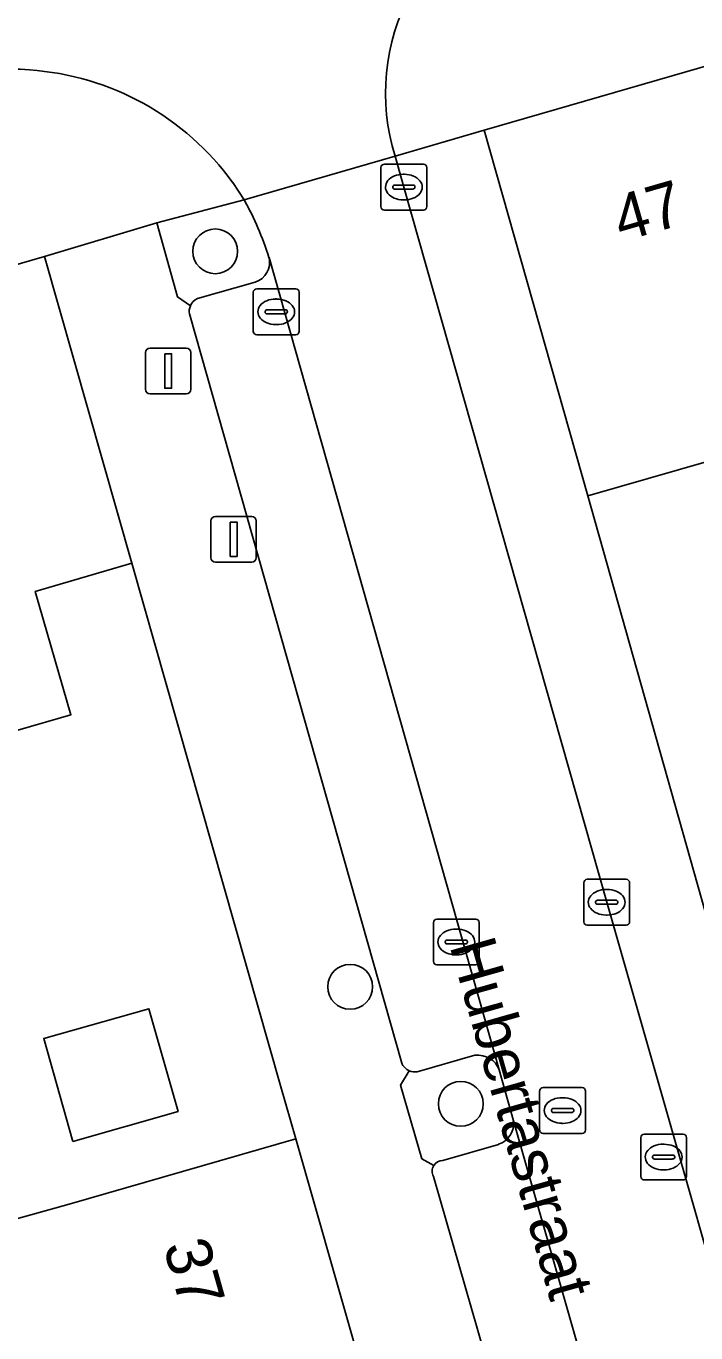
# Model space of a CAD drawing. Extents: x 159716 to 160783, y 383290 to 384031.
# Drawn here: x 160271.18 to 160285.8, y 383552.15 to 383580.67 of the extents above; entities that cross this region are included whole.
import ezdxf

# ---------------------------------------------------------------- set-up
doc = ezdxf.new("R2010")
doc.units = 0
for name, color, linetype in [('IMGEO_Boom', 7, 'Continuous'), ('IMGEO_Erf', 7, 'Continuous'), ('IMGEO_Groenvoorziening', 7, 'Continuous'), ('IMGEO_Kolk', 7, 'Continuous'), ('IMGEO_Lichtmast', 7, 'Continuous'), ('IMGEO_Muur', 7, 'Continuous'), ('IMGEO_Openbare_ruimte_label', 7, 'Continuous'), ('IMGEO_Pand', 7, 'Continuous'), ('IMGEO_Pand_nummerreeks', 7, 'Continuous'), ('IMGEO_Parkeervlak_open', 7, 'Continuous'), ('IMGEO_Rijbaan_lokaal_open', 7, 'Continuous'), ('IMGEO_Rioolput', 7, 'Continuous'), ('IMGEO_Voetpad_open', 7, 'Continuous')]:
    doc.layers.add(name, color=color, linetype=linetype)

msp = doc.modelspace()

# ---------------------------------------------------------------- linework, layer by layer
at = {"layer": 'IMGEO_Boom'}
for centre in [(160275.308, 383575.752), (160278.253, 383559.705), (160280.666, 383557.152)]:
    msp.add_circle(centre, 0.489, dxfattribs=at)
at = {"layer": 'IMGEO_Erf'}
msp.add_lwpolyline([(160268.034, 383551.618), (160270.468, 383552.309), (160269.9, 383554.344), (160272.122, 383554.966), (160277.064, 383556.388), (160276.741, 383557.524), (160273.488, 383568.945), (160271.382, 383568.331), (160272.16, 383565.64), (160269.84, 383564.97), (160267.609, 383564.325), (160266.888, 383566.818), (160264.783, 383566.21), (160262.981, 383565.69), (160263.98, 383562.232), (160263.607, 383562.124), (160264.309, 383559.691), (160261.816, 383558.972), (160261.114, 383561.405), (160261.327, 383561.466), (160259.212, 383568.791), (160258.339, 383571.813), (160253.089, 383570.307)], dxfattribs=at)
msp.add_lwpolyline([(160272.203, 383556.33), (160271.566, 383558.576), (160273.863, 383559.227), (160274.5, 383556.981)], close=True, dxfattribs=at)
at = {"layer": 'IMGEO_Groenvoorziening'}
for points in [[(160275.937, 383576.879), (160274.036, 383576.37), (160274.482, 383574.759), (160274.767, 383574.565)], [(160274.921, 383574.725), (160276.181, 383575.08)], [(160280.976, 383558.21), (160279.714, 383557.851)], [(160279.543, 383557.873), (160279.353, 383557.556), (160279.815, 383555.952), (160280.076, 383555.805)], [(160281.816, 383556.782), (160281.507, 383557.891)], [(160280.272, 383555.916), (160281.487, 383556.268)]]:
    msp.add_lwpolyline(points, dxfattribs=at)
for centre, radius, start, end in [((160269.885, 383573.517), 6.923, 17.6598, 29.0548), ((160276.04, 383575.512), 0.455, 288.1084, 13.3484), ((160275.053, 383574.444), 0.311, 115.1578, 157.0315), ((160281.035, 383557.707), 0.507, 21.337, 96.672), ((160279.667, 383558.161), 0.313, 246.6975, 278.6402), ((160281.349, 383556.719), 0.471, 287.021, 7.7342), ((160280.274, 383555.683), 0.233, 90.5607, 148.4873)]:
    msp.add_arc(centre, radius, start, end, dxfattribs=at)
at = {"layer": 'IMGEO_Kolk'}
for p, q in [((160278.924, 383576.727), (160278.924, 383577.579)), ((160278.999, 383577.653), (160279.851, 383577.653)), ((160279.925, 383577.579), (160279.925, 383576.727)), ((160279.412, 383577.433), (160279.437, 383577.433)), ((160279.183, 383577.147), (160279.183, 383577.159)), ((160279.621, 383577.11), (160279.223, 383577.11)), ((160279.226, 383577.196), (160279.624, 383577.196)), ((160279.667, 383577.159), (160279.667, 383577.147)), ((160279.851, 383576.653), (160278.999, 383576.653)), ((160279.435, 383576.873), (160279.41, 383576.873)), ((160276.214, 383574.932), (160277.066, 383574.932)), ((160276.139, 383574.006), (160276.139, 383574.858)), ((160276.627, 383574.712), (160276.652, 383574.712)), ((160277.14, 383574.858), (160277.14, 383574.006)), ((160276.398, 383574.426), (160276.398, 383574.438)), ((160276.836, 383574.389), (160276.438, 383574.389)), ((160276.441, 383574.475), (160276.839, 383574.475)), ((160276.882, 383574.438), (160276.882, 383574.426)), ((160276.65, 383574.152), (160276.625, 383574.152)), ((160277.066, 383573.932), (160276.214, 383573.932)), ((160283.349, 383561.124), (160283.349, 383561.976)), ((160283.424, 383562.05), (160284.276, 383562.05)), ((160283.837, 383561.83), (160283.862, 383561.83)), ((160284.35, 383561.976), (160284.35, 383561.124)), ((160283.608, 383561.544), (160283.608, 383561.556)), ((160283.651, 383561.593), (160284.049, 383561.593)), ((160284.092, 383561.556), (160284.092, 383561.544)), ((160284.046, 383561.507), (160283.648, 383561.507)), ((160283.86, 383561.27), (160283.835, 383561.27)), ((160280.068, 383560.257), (160280.068, 383561.109)), ((160280.143, 383561.183), (160280.995, 383561.183)), ((160280.556, 383560.963), (160280.581, 383560.963)), ((160281.069, 383561.109), (160281.069, 383560.257)), ((160284.276, 383561.05), (160283.424, 383561.05)), ((160280.327, 383560.677), (160280.327, 383560.689)), ((160280.37, 383560.726), (160280.768, 383560.726)), ((160280.811, 383560.689), (160280.811, 383560.677)), ((160280.765, 383560.64), (160280.367, 383560.64)), ((160280.579, 383560.403), (160280.554, 383560.403)), ((160280.995, 383560.183), (160280.143, 383560.183))]:
    msp.add_line(p, q, dxfattribs=at)
for points in [[(160278.924, 383576.727), (160278.924, 383577.579)], [(160278.999, 383577.653), (160279.851, 383577.653)], [(160279.925, 383577.579), (160279.925, 383576.727)], [(160279.851, 383576.653), (160278.999, 383576.653)], [(160276.214, 383574.932), (160277.066, 383574.932)], [(160276.139, 383574.006), (160276.139, 383574.858)], [(160277.14, 383574.858), (160277.14, 383574.006)], [(160277.066, 383573.932), (160276.214, 383573.932)], [(160283.349, 383561.124), (160283.349, 383561.976)], [(160283.424, 383562.05), (160284.276, 383562.05)], [(160284.35, 383561.976), (160284.35, 383561.124)], [(160280.068, 383560.257), (160280.068, 383561.109)], [(160280.143, 383561.183), (160280.995, 383561.183)], [(160281.069, 383561.109), (160281.069, 383560.257)], [(160284.276, 383561.05), (160283.424, 383561.05)], [(160280.995, 383560.183), (160280.143, 383560.183)]]:
    msp.add_lwpolyline(points, dxfattribs=at)
for centre, radius, start, end in [((160279.001, 383577.577), 0.0765, 91.552, 178.448), ((160279.001, 383577.577), 0.0765, 91.552, 178.448), ((160279.849, 383577.577), 0.0765, 1.552, 88.448), ((160279.849, 383577.577), 0.0765, 1.552, 88.448), ((160279.223, 383577.156), 0.0403, 85.8775, 175.7526), ((160279.22, 383577.146), 0.0366, 178.938, 274.7102), ((160279.624, 383577.153), 0.043, 264.8664, 352.4533), ((160279.628, 383577.158), 0.0386, 1.7309, 96.639), ((160279.001, 383576.729), 0.0765, 181.552, 268.448), ((160279.001, 383576.729), 0.0765, 181.552, 268.448), ((160279.849, 383576.729), 0.0765, 271.552, 358.448), ((160279.849, 383576.729), 0.0765, 271.552, 358.448), ((160276.216, 383574.856), 0.0765, 91.552, 178.448), ((160276.216, 383574.856), 0.0765, 91.552, 178.448), ((160277.064, 383574.856), 0.0765, 1.552, 88.448), ((160277.064, 383574.856), 0.0765, 1.552, 88.448), ((160276.438, 383574.435), 0.0403, 85.8775, 175.7526), ((160276.435, 383574.425), 0.0366, 178.938, 274.7102), ((160276.839, 383574.432), 0.043, 264.8664, 352.4533), ((160276.843, 383574.437), 0.0386, 1.7309, 96.639), ((160276.216, 383574.008), 0.0765, 181.552, 268.448), ((160276.216, 383574.008), 0.0765, 181.552, 268.448), ((160277.064, 383574.008), 0.0765, 271.552, 358.448), ((160277.064, 383574.008), 0.0765, 271.552, 358.448), ((160283.426, 383561.974), 0.0765, 91.552, 178.448), ((160283.426, 383561.974), 0.0765, 91.552, 178.448), ((160284.274, 383561.974), 0.0765, 1.552, 88.448), ((160284.274, 383561.974), 0.0765, 1.552, 88.448), ((160283.648, 383561.553), 0.0403, 85.8775, 175.7526), ((160283.645, 383561.543), 0.0366, 178.938, 274.7102), ((160284.049, 383561.55), 0.043, 264.8664, 352.4533), ((160284.053, 383561.555), 0.0386, 1.7309, 96.639), ((160280.145, 383561.107), 0.0765, 91.552, 178.448), ((160280.145, 383561.107), 0.0765, 91.552, 178.448), ((160280.993, 383561.107), 0.0765, 1.552, 88.448), ((160280.993, 383561.107), 0.0765, 1.552, 88.448), ((160283.426, 383561.126), 0.0765, 181.552, 268.448), ((160283.426, 383561.126), 0.0765, 181.552, 268.448), ((160284.274, 383561.126), 0.0765, 271.552, 358.448), ((160284.274, 383561.126), 0.0765, 271.552, 358.448), ((160280.367, 383560.686), 0.0403, 85.8775, 175.7526), ((160280.364, 383560.676), 0.0366, 178.938, 274.7102), ((160280.768, 383560.683), 0.043, 264.8664, 352.4533), ((160280.772, 383560.688), 0.0386, 1.7309, 96.639), ((160280.145, 383560.259), 0.0765, 181.552, 268.448), ((160280.145, 383560.259), 0.0765, 181.552, 268.448), ((160280.993, 383560.259), 0.0765, 271.552, 358.448), ((160280.993, 383560.259), 0.0765, 271.552, 358.448)]:
    msp.add_arc(centre, radius, start, end, dxfattribs=at)
for centre, major_axis, ratio, start_param, end_param in [((160279.411, 383577.153), (-0.387, 0.002), 0.722429, 4.712389, 7.853982), ((160279.436, 383577.153), (-0.39, 0.002), 0.717154, 1.570796, 4.712389), ((160276.626, 383574.432), (-0.387, 0.002), 0.722429, 4.712389, 7.853982), ((160276.651, 383574.432), (-0.39, 0.002), 0.717154, 1.570796, 4.712389), ((160283.836, 383561.55), (-0.387, 0.002), 0.722429, 4.712389, 7.853982), ((160283.861, 383561.55), (-0.39, 0.002), 0.717154, 1.570796, 4.712389), ((160280.555, 383560.683), (-0.387, 0.002), 0.722429, 4.712389, 7.853982), ((160280.58, 383560.683), (-0.39, 0.002), 0.717154, 1.570796, 4.712389)]:
    msp.add_ellipse(centre, major_axis=major_axis, ratio=ratio, start_param=start_param, end_param=end_param, dxfattribs=at)
at = {"layer": 'IMGEO_Lichtmast'}
for p, q in [((160273.787, 383572.741), (160273.787, 383573.541)), ((160273.787, 383573.541), (160273.787, 383572.741)), ((160273.887, 383573.641), (160274.677, 383573.641)), ((160274.677, 383573.641), (160273.887, 383573.641)), ((160274.777, 383573.541), (160274.777, 383572.741)), ((160274.777, 383572.741), (160274.777, 383573.541)), ((160274.677, 383572.641), (160273.887, 383572.641)), ((160273.887, 383572.641), (160274.677, 383572.641)), ((160275.215, 383569.069), (160275.215, 383569.869)), ((160275.215, 383569.869), (160275.215, 383569.069)), ((160275.315, 383569.969), (160276.105, 383569.969)), ((160276.105, 383569.969), (160275.315, 383569.969)), ((160276.205, 383569.869), (160276.205, 383569.069)), ((160276.205, 383569.069), (160276.205, 383569.869)), ((160276.105, 383568.969), (160275.315, 383568.969)), ((160275.315, 383568.969), (160276.105, 383568.969))]:
    msp.add_line(p, q, dxfattribs=at)
for points in [[(160274.207, 383573.516), (160274.357, 383573.516), (160274.357, 383572.766), (160274.207, 383572.766), (160274.207, 383573.516)], [(160275.635, 383569.844), (160275.785, 383569.844), (160275.785, 383569.094), (160275.635, 383569.094), (160275.635, 383569.844)]]:
    msp.add_lwpolyline(points, dxfattribs=at)
for centre, start, end in [((160273.887, 383573.541), 90, 180), ((160273.887, 383573.541), 90, 180), ((160274.677, 383573.541), 0, 90), ((160274.677, 383573.541), 360, 90), ((160273.887, 383572.741), 180, 270), ((160273.887, 383572.741), 180, 270), ((160274.677, 383572.741), 270, 0), ((160274.677, 383572.741), 270, 0), ((160275.315, 383569.869), 90, 180), ((160275.315, 383569.869), 90, 180), ((160276.105, 383569.869), 0, 90), ((160276.105, 383569.869), 360, 90), ((160275.315, 383569.069), 180, 270), ((160275.315, 383569.069), 180, 270), ((160276.105, 383569.069), 270, 0), ((160276.105, 383569.069), 270, 0)]:
    msp.add_arc(centre, 0.1, start, end, dxfattribs=at)
at = {"layer": 'IMGEO_Muur'}
msp.add_lwpolyline([(160273.488, 383568.945), (160276.741, 383557.524)], dxfattribs=at)
at = {"layer": 'IMGEO_Pand'}
for points in [[(160287.143, 383580.116), (160281.178, 383578.396), (160283.435, 383570.416), (160289.437, 383572.141), (160289.1, 383573.311), (160289.054, 383573.472)], [(160271.583, 383575.638), (160267.131, 383574.352), (160269.84, 383564.97), (160272.16, 383565.64), (160271.382, 383568.331), (160273.488, 383568.945)], [(160289.437, 383572.141), (160283.435, 383570.416), (160286.088, 383561.038), (160290.795, 383562.491), (160292.104, 383562.867)], [(160272.203, 383556.33), (160274.5, 383556.981), (160273.863, 383559.227), (160271.566, 383558.576)], [(160277.064, 383556.388), (160272.122, 383554.966), (160269.9, 383554.344), (160270.468, 383552.309), (160268.034, 383551.618), (160268.721, 383549.198), (160269.134, 383549.315), (160278.343, 383551.929)]]:
    msp.add_lwpolyline(points, close=True, dxfattribs=at)
at = {"layer": 'IMGEO_Parkeervlak_open'}
for points in [[(160281.507, 383557.891), (160276.482, 383575.617)], [(160276.181, 383575.08), (160274.921, 383574.725)], [(160274.746, 383574.386), (160279.377, 383558.042)], [(160279.714, 383557.851), (160280.976, 383558.21)], [(160286.865, 383539.129), (160281.816, 383556.782)], [(160281.487, 383556.268), (160280.272, 383555.916)], [(160280.073, 383555.569), (160284.772, 383539.246)]]:
    msp.add_lwpolyline(points, dxfattribs=at)
for centre, radius, start, end in [((160276.04, 383575.512), 0.455, 288.1084, 13.3484), ((160275.053, 383574.444), 0.311, 115.1578, 157.0315), ((160275.047, 383574.441), 0.306, 156.1654, 190.452), ((160281.035, 383557.707), 0.507, 21.337, 96.672), ((160279.663, 383558.157), 0.308, 201.8658, 247.108), ((160279.667, 383558.161), 0.313, 246.6975, 278.6402), ((160281.349, 383556.719), 0.471, 287.021, 7.7342), ((160280.274, 383555.683), 0.233, 90.5607, 148.4873), ((160280.272, 383555.684), 0.231, 148.4785, 210.0649)]:
    msp.add_arc(centre, radius, start, end, dxfattribs=at)
at = {"layer": 'IMGEO_Rijbaan_lokaal_open'}
for points in [[(160275.692, 383577.25), (160275.937, 383576.879), (160279.234, 383577.826)], [(160279.425, 383577.153), (160279.234, 383577.826), (160275.937, 383576.879)], [(160276.482, 383575.617), (160281.507, 383557.891), (160281.816, 383556.782), (160286.865, 383539.129), (160286.882, 383539.069), (160287.171, 383538.067), (160288.383, 383533.677), (160291.545, 383534.548), (160291.476, 383534.792), (160287.815, 383547.679), (160283.85, 383561.55), (160279.425, 383577.153)]]:
    msp.add_lwpolyline(points, dxfattribs=at)
for centre, radius, start, end in [((160283.618, 383579.204), 4.595, 105.6277, 197.4451), ((160270.877, 383575.725), 4.003, 84.5477, 96.2918), ((160270.856, 383573.759), 5.964, 35.8232, 86.1444), ((160269.885, 383573.517), 6.923, 17.6598, 29.0548)]:
    msp.add_arc(centre, radius, start, end, dxfattribs=at)
at = {"layer": 'IMGEO_Rioolput'}
for p, q in [((160282.387, 383556.58), (160282.387, 383557.432)), ((160282.462, 383557.506), (160283.314, 383557.506)), ((160282.875, 383557.286), (160282.9, 383557.286)), ((160283.388, 383557.432), (160283.388, 383556.58)), ((160282.646, 383557), (160282.646, 383557.012)), ((160282.689, 383557.049), (160283.087, 383557.049)), ((160283.13, 383557.012), (160283.13, 383557)), ((160283.084, 383556.963), (160282.686, 383556.963)), ((160282.898, 383556.726), (160282.873, 383556.726)), ((160283.314, 383556.506), (160282.462, 383556.506)), ((160284.592, 383555.565), (160284.592, 383556.417)), ((160284.667, 383556.491), (160285.519, 383556.491)), ((160285.593, 383556.417), (160285.593, 383555.565)), ((160285.08, 383556.271), (160285.105, 383556.271)), ((160284.851, 383555.985), (160284.851, 383555.997)), ((160285.289, 383555.948), (160284.891, 383555.948)), ((160284.894, 383556.034), (160285.292, 383556.034)), ((160285.335, 383555.997), (160285.335, 383555.985)), ((160285.103, 383555.711), (160285.078, 383555.711)), ((160285.519, 383555.491), (160284.667, 383555.491))]:
    msp.add_line(p, q, dxfattribs=at)
for points in [[(160282.387, 383556.58), (160282.387, 383557.432)], [(160282.462, 383557.506), (160283.314, 383557.506)], [(160283.388, 383557.432), (160283.388, 383556.58)], [(160283.314, 383556.506), (160282.462, 383556.506)], [(160284.592, 383555.565), (160284.592, 383556.417)], [(160284.667, 383556.491), (160285.519, 383556.491)], [(160285.593, 383556.417), (160285.593, 383555.565)], [(160285.519, 383555.491), (160284.667, 383555.491)]]:
    msp.add_lwpolyline(points, dxfattribs=at)
for centre, radius, start, end in [((160282.464, 383557.43), 0.0765, 91.552, 178.448), ((160282.464, 383557.43), 0.0765, 91.552, 178.448), ((160283.312, 383557.43), 0.0765, 1.552, 88.448), ((160283.312, 383557.43), 0.0765, 1.552, 88.448), ((160282.686, 383557.009), 0.0403, 85.8775, 175.7526), ((160282.683, 383556.999), 0.0366, 178.938, 274.7102), ((160283.087, 383557.006), 0.043, 264.8664, 352.4533), ((160283.091, 383557.011), 0.0386, 1.7309, 96.639), ((160282.464, 383556.582), 0.0765, 181.552, 268.448), ((160282.464, 383556.582), 0.0765, 181.552, 268.448), ((160283.312, 383556.582), 0.0765, 271.552, 358.448), ((160283.312, 383556.582), 0.0765, 271.552, 358.448), ((160284.669, 383556.415), 0.0765, 91.552, 178.448), ((160284.669, 383556.415), 0.0765, 91.552, 178.448), ((160285.517, 383556.415), 0.0765, 1.552, 88.448), ((160285.517, 383556.415), 0.0765, 1.552, 88.448), ((160284.891, 383555.994), 0.0403, 85.8775, 175.7526), ((160284.888, 383555.984), 0.0366, 178.938, 274.7102), ((160285.292, 383555.991), 0.043, 264.8664, 352.4533), ((160285.296, 383555.996), 0.0386, 1.7309, 96.639), ((160284.669, 383555.567), 0.0765, 181.552, 268.448), ((160284.669, 383555.567), 0.0765, 181.552, 268.448), ((160285.517, 383555.567), 0.0765, 271.552, 358.448), ((160285.517, 383555.567), 0.0765, 271.552, 358.448)]:
    msp.add_arc(centre, radius, start, end, dxfattribs=at)
for centre, major_axis, ratio, start_param, end_param in [((160282.874, 383557.006), (-0.387, 0.002), 0.722429, 4.712389, 7.853982), ((160282.899, 383557.006), (-0.39, 0.002), 0.717154, 1.570796, 4.712389), ((160285.079, 383555.991), (-0.387, 0.002), 0.722429, 4.712389, 7.853982), ((160285.104, 383555.991), (-0.39, 0.002), 0.717154, 1.570796, 4.712389)]:
    msp.add_ellipse(centre, major_axis=major_axis, ratio=ratio, start_param=start_param, end_param=end_param, dxfattribs=at)
at = {"layer": 'IMGEO_Voetpad_open'}
for points in [[(160279.234, 383577.826), (160281.178, 383578.396), (160287.143, 383580.116)], [(160286.088, 383561.038), (160283.435, 383570.416), (160281.178, 383578.396), (160279.234, 383577.826), (160279.425, 383577.153), (160283.85, 383561.55), (160287.815, 383547.679), (160291.476, 383534.792), (160291.545, 383534.548), (160292.474, 383531.266)], [(160206.481, 383559.908), (160207.569, 383560.131), (160208.331, 383560.287), (160208.467, 383560.285), (160209.46, 383556.921), (160211.542, 383557.498), (160216.391, 383558.613), (160219.583, 383559.225), (160253.749, 383567.499), (160253.089, 383570.307), (160258.339, 383571.813), (160262.793, 383573.1), (160267.131, 383574.352), (160271.583, 383575.638), (160274.036, 383576.37), (160275.937, 383576.879), (160275.692, 383577.25)], [(160274.767, 383574.565), (160274.482, 383574.759), (160274.036, 383576.37), (160271.583, 383575.638), (160273.488, 383568.945), (160276.741, 383557.524), (160277.064, 383556.388), (160278.343, 383551.929), (160279.583, 383547.604), (160280.824, 383543.279), (160282.064, 383538.954), (160283.305, 383534.629), (160284.545, 383530.303), (160285.829, 383525.827)], [(160279.377, 383558.042), (160274.746, 383574.386)], [(160280.076, 383555.805), (160279.815, 383555.952), (160279.353, 383557.556), (160279.543, 383557.873)], [(160284.772, 383539.246), (160280.073, 383555.569)]]:
    msp.add_lwpolyline(points, dxfattribs=at)
for centre, radius, start, end in [((160283.618, 383579.204), 4.595, 105.6277, 197.4451), ((160270.877, 383575.725), 4.003, 84.5477, 96.2918), ((160270.856, 383573.759), 5.964, 35.8232, 86.1444), ((160275.047, 383574.441), 0.306, 156.1654, 190.452), ((160279.663, 383558.157), 0.308, 201.8658, 247.108), ((160280.272, 383555.684), 0.231, 148.4785, 210.0649)]:
    msp.add_arc(centre, radius, start, end, dxfattribs=at)

# ---------------------------------------------------------------- texts
at = {"layer": 'IMGEO_Openbare_ruimte_label'}
msp.add_text('Hubertastraat', height=1, rotation=285.8431, dxfattribs=at).set_placement((160280.416, 383560.606))
at = {"layer": 'IMGEO_Pand_nummerreeks'}
for s, rotation, p in [('47', 16.0543, (160284.17, 383575.953)), ('37', 285.8363, (160274.17, 383554.049))]:
    msp.add_text(s, height=1, rotation=rotation, dxfattribs=at).set_placement(p)

doc.saveas('drawing.dxf')
